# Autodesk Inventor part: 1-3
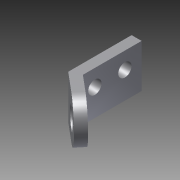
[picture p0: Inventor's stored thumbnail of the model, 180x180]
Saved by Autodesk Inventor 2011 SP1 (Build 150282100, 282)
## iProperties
Created: 2014-01
Part Number: 1-3
Document SubType Name: Modeling
Designer: Administrator
Density: 1 g/cm^3
Author: Administrator
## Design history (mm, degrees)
sketch "草图1"
  geometry: L1 (-3, 19)-(-3, -19); L2 (-3, -19)-(8.491, -28.642); L3 (-3, 19)-(3, 19); L4 (8.491, -28.642)-(12.347, -24.046); L5 (12.347, -24.046)-(3, -16.202); L6 (3, -16.202)-(3, 19); 3 further points
  constraints: 12 end point, 3 perpendicular, 2 midpoint, 1 horizontal alignment, 1 vertical, 1 vertical alignment
  dimensions: "d0" = 38 distance of L1.start L1.end; "d1" = 15 distance of L1.end L2.end; "d2" = 6 distance of L1.start L3.end; "d3" = 6 distance of L2.end L4.end; "d4" = 130 deg angle of L6 L5; "d5" = 130 deg angle of L1 L2
extrude "拉伸1" new body sketch "草图1" distance "d6" = 26; taper "d7" = 0 deg
sketch "草图2"
  geometry: L1 (15, 0)-(15, 26) reference; L2 (15, 26)-(15, 0); A1 r 13 centre (15, 13) between (15, 0) and (15, 26); 1 further point
  constraints: 4 end point, 2 point on circle, 1 centre point, 1 collinear, 1 midpoint
extrude "拉伸2" join sketch "草图2" distance "d8" = 6; taper "d9" = 0 deg
hole "Hole1" diameter "d12" = 13; stored, may be unused: countersink angle "d16" = 90 deg, drill point angle "d18" = 0 deg; dims "d10" = 10, "d11" = 10, "d13" = 6, "d14" = 4, "d15" = 2, "d17" = 8
sketch "草图3"
  geometry: L1 (3, 19)-(3, -19) reference; L2 (3, 10)-(3, -13); L3 (3, 19)-(3, 10); L4 (3, 19)-(13, 19); L5 (3, -13)-(19.416, 3.689); A1 r 9 centre (13, 10) between (19.416, 3.689) and (13, 19); 1 further point
  constraints: 8 end point, 2 point on circle, 2 tangent, 1 centre point, 1 point on line
  dimensions: "d19" = 32 distance of L1.start L2.end; "d20" = 9 distance of L1.start L2.start; "d22" = 18 diameter of A1
extrude "拉伸3" join sketch "草图3" distance "d23" = 6; taper "d24" = 0 deg
hole "Hole2" diameter "d27" = 8; stored, may be unused: countersink angle "d31" = 90 deg, drill point angle "d33" = 0 deg; dims "d25" = 10, "d26" = 10, "d28" = 6, "d29" = 4, "d30" = 2, "d32" = 8
hole "Hole3" diameter "d36" = 8; stored, may be unused: countersink angle "d40" = 90 deg, drill point angle "d42" = 118 deg; dims "d34" = 10, "d35" = 10, "d37" = 6, "d38" = 4, "d39" = 2, "d41" = 8
hole "Hole4" diameter "d45" = 8; stored, may be unused: countersink angle "d49" = 90 deg, drill point angle "d51" = 118 deg; dims "d43" = 10, "d44" = 10, "d46" = 6, "d47" = 4, "d48" = 2, "d50" = 8
node "实体1"
